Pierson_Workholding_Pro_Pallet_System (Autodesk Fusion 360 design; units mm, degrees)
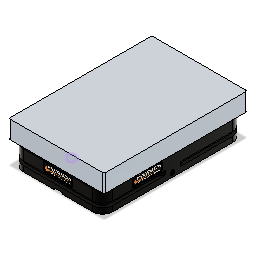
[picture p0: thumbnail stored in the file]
base_feature "Base Feature1"
base_feature "Base Feature1"
base_feature "Base Feature1"
joint "Assemble1" alignAngle 0 alignOffsetX 0 alignOffsetY 0 alignOffsetZ 0
joint "Assemble2" alignAngle -180 alignOffsetX 0 alignOffsetY 0 alignOffsetZ 0
joint "Assemble3" alignAngle 180 alignOffsetX 0 alignOffsetY 0 alignOffsetZ 0
joint "Assemble4" alignAngle 0 alignOffsetX 0 alignOffsetY 0 alignOffsetZ 0
base_feature "Base Feature1"
base_feature "Base Feature1"
sketch "Sketch1" plane through (0, 0, 0.254) normal (0, 0, -1) x axis (1, 0, 0)
  line L1 (161.29, -123.825) -> (161.29, -28.575)
  line L2 (181.61, -28.575) -> (181.61, -123.825)
  arc A1 centre (171.45, -28.575) radius 10.16 clockwise from (161.29, -28.575) to (181.61, -28.575)
  arc A2 centre (171.45, -123.825) radius 10.16 clockwise from (181.61, -123.825) to (161.29, -123.825)
  circle C1 centre (101.6, -31.75) radius 11.129
joint_origin "JointOrigin1" OffsetX 0 OffsetY 0 OffsetZ 0 AngleZ 0
sketch "Sketch1" plane through (11.8969, 0.127, 8.8047) normal (0, -1, 0) x axis (1, 0, 0)
  line L1 (149.3931, -132.6297) -> (149.3931, -37.3797)
  line L2 (169.7131, -37.3797) -> (169.7131, -132.6297)
  arc A1 centre (159.5531, -37.3797) radius 10.16 clockwise from (149.3931, -37.3797) to (169.7131, -37.3797)
  arc A2 centre (159.5531, -132.6297) radius 10.16 clockwise from (169.7131, -132.6297) to (149.3931, -132.6297)
  circle C1 centre (89.7031, -40.5547) radius 11.129
joint_origin "JointOrigin2" OffsetX 0 OffsetY 0 OffsetZ 0 AngleZ 0
sketch "Sketch1" plane through (0, 48.26, 0) normal (0, 1, 0) x axis (-1, 0, 0)
  line L1 (-33.6804, -120.65) -> (-33.6804, -25.4)
  line L2 (-17.1196, -25.4) -> (-17.1196, -120.65)
  arc A1 centre (-25.4, -25.4) radius 8.2804 clockwise from (-33.6804, -25.4) to (-17.1196, -25.4)
  arc A2 centre (-25.4, -120.65) radius 8.2804 clockwise from (-17.1196, -120.65) to (-33.6804, -120.65)
  circle C1 centre (-95.25, -28.575) radius 7.9375
joint_origin "JointOrigin7" OffsetX 0 OffsetY 0 OffsetZ 0 AngleZ 0
joint "Assemble4" alignAngle 0 alignOffsetX 0 alignOffsetY 0 alignOffsetZ 0
joint "Assemble5" alignAngle 0 alignOffsetX 0 alignOffsetY 0 alignOffsetZ 0
base_feature "Base Feature1"
sketch "Sketch1" plane through (0, 0, 0.254) normal (0, 0, -1) x axis (1, 0, 0)
  line L1 (161.29, -123.825) -> (161.29, -28.575)
  line L2 (181.61, -28.575) -> (181.61, -123.825)
  arc A1 centre (171.45, -28.575) radius 10.16 clockwise from (161.29, -28.575) to (181.61, -28.575)
  arc A2 centre (171.45, -123.825) radius 10.16 clockwise from (181.61, -123.825) to (161.29, -123.825)
  circle C1 centre (101.6, -31.75) radius 11.129
joint_origin "JointOrigin1" OffsetX 0 OffsetY 0 OffsetZ 0 AngleZ 0
joint "Assemble6" alignAngle 0 alignOffsetX 0 alignOffsetY 0 alignOffsetZ 0
base_feature "Base Feature1"
sketch "Sketch1" plane through (0, 0, 0.254) normal (0, 0, -1) x axis (1, 0, 0)
  line L1 (161.29, -123.825) -> (161.29, -28.575)
  line L2 (181.61, -28.575) -> (181.61, -123.825)
  arc A1 centre (171.45, -28.575) radius 10.16 clockwise from (161.29, -28.575) to (181.61, -28.575)
  arc A2 centre (171.45, -123.825) radius 10.16 clockwise from (181.61, -123.825) to (161.29, -123.825)
  circle C1 centre (101.6, -31.75) radius 11.129
joint_origin "JointOrigin1" OffsetX 0 OffsetY 0 OffsetZ 0 AngleZ 0
joint "Assemble7" alignAngle 0 alignOffsetX 0 alignOffsetY 0 alignOffsetZ 0
sketch "Base" plane through (0, 0, 0) normal (0, 1, 0) x axis (1, 0, 0)
  circle C1 centre (0, 0) radius 12.7
  point P1 (0, 0)
  point P2 (0, 0)
  coincident P1 P2
  dimension "d233" diameter C1 = 25.4
ground "Ground4"
joint "Assemble9" alignAngle 0 alignOffsetX 0 alignOffsetY 0 alignOffsetZ 0
sketch "ORIGIN_CNC-Machine" plane through (0, 48.26, 0) normal (0, 1, 0) x axis (-1, 0, 0)
  line L1 (61.5696, -41.275) -> (61.5696, 53.975)
  line L2 (78.1304, 53.975) -> (78.1304, -41.275)
  arc A1 centre (69.85, 53.975) radius 8.2804 clockwise from (61.5696, 53.975) to (78.1304, 53.975)
  arc A2 centre (69.85, -41.275) radius 8.2804 clockwise from (78.1304, -41.275) to (61.5696, -41.275)
  circle C1 centre (0, 50.8) radius 7.9375
fillet "Fillet1" radius 3.175
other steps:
create_component "CreateComponent1"
create_component "CreateComponent1"
joint_origin "JointOrigin1" OffsetX 0 OffsetY 0 OffsetZ 0 AngleZ 0
joint_origin "JointOrigin1" OffsetX 0 OffsetY 0 OffsetZ 0 AngleZ 0
joint_origin "JointOrigin2" OffsetX 0 OffsetY 0 OffsetZ 0 AngleZ 0
joint_origin "JointOrigin2" OffsetX 0 OffsetY 0 OffsetZ 0 AngleZ 0
joint_origin "JointOrigin3" OffsetX 0 OffsetY 0 OffsetZ 0 AngleZ 0
joint_origin "JointOrigin3" OffsetX 0 OffsetY 0 OffsetZ 0 AngleZ 0
joint_origin "JointOrigin4" OffsetX 0 OffsetY 0 OffsetZ 0 AngleZ 0
joint_origin "JointOrigin4" OffsetX 0 OffsetY 0 OffsetZ 0 AngleZ 0
create_component "CreateComponent2"
create_component "CreateComponent3"
create_component "CreateComponent4"
create_component "CreateComponent5"
joint_origin "JointOrigin8"
joint_origin "JointOrigin11"
joint_origin "JointOrigin8"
